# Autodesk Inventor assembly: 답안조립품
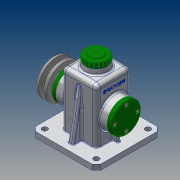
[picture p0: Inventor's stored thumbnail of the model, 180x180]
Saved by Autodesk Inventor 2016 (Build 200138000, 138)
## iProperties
Created: 2018-10
Part Number: 답안조립품
Material: 일반
Document SubType Name: Assembly
Designer: user
Author: user
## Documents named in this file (14)
- C:\Users\user\Desktop\481016V1015\답안조립품.iam
- C:\Users\user\Desktop\481016V1015\본체.ipt
- C:\Users\user\Desktop\481016V1015\베어링 15 x 35 x 11.ipt
- C:\Users\user\Desktop\481016V1015\축.ipt
- C:\Users\user\Desktop\481016V1015\멈춤링 15 x 1.ipt
- C:\Users\user\Desktop\481016V1015\뒤커버.ipt
- C:\Users\user\Desktop\481016V1015\앞커버.ipt
- C:\Users\user\Desktop\481016V1015\볼트 M4 x 10.ipt
- C:\Users\user\Desktop\481016V1015\상부캡.ipt
- C:\Users\user\Desktop\481016V1015\키 5 x 5 x 14.ipt
- C:\Users\user\Desktop\481016V1015\V-벨트풀리.ipt
- C:\Users\user\Desktop\481016V1015\와셔.ipt
- C:\Users\user\Desktop\481016V1015\볼트 M6 x 12.ipt
- C:\Users\user\Desktop\481016V1015\오일실 15 25 7.ipt
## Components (1 placed, 1 different names)
1. V-벨트풀리:1
